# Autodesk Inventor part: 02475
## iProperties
Author: Administrator
Shininess: 64.0
Angle Display Precision: 2
Document Length Units: 11272
Document Angle Units: 11286
Document Time Units: 11279
Document Mass Units: 11290
Document Length Units Precision: 3
Document Angle Units Precision: 2
Compacted: True
PropertySet Name: _Private Model Information
Created: 2002-04
Part Number: 02475
Material: Stainless Steel, 440C
Document SubType Name: Modeling
Designer: Administrator
Control State: 0
Master: False
Checked Out: False
PropertySet Name: Design Tracking Control
Density: 0.0
Volumn: 0.0
Area: 0.0
PropertySet Name: Model Information
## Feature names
1. Revolution1
